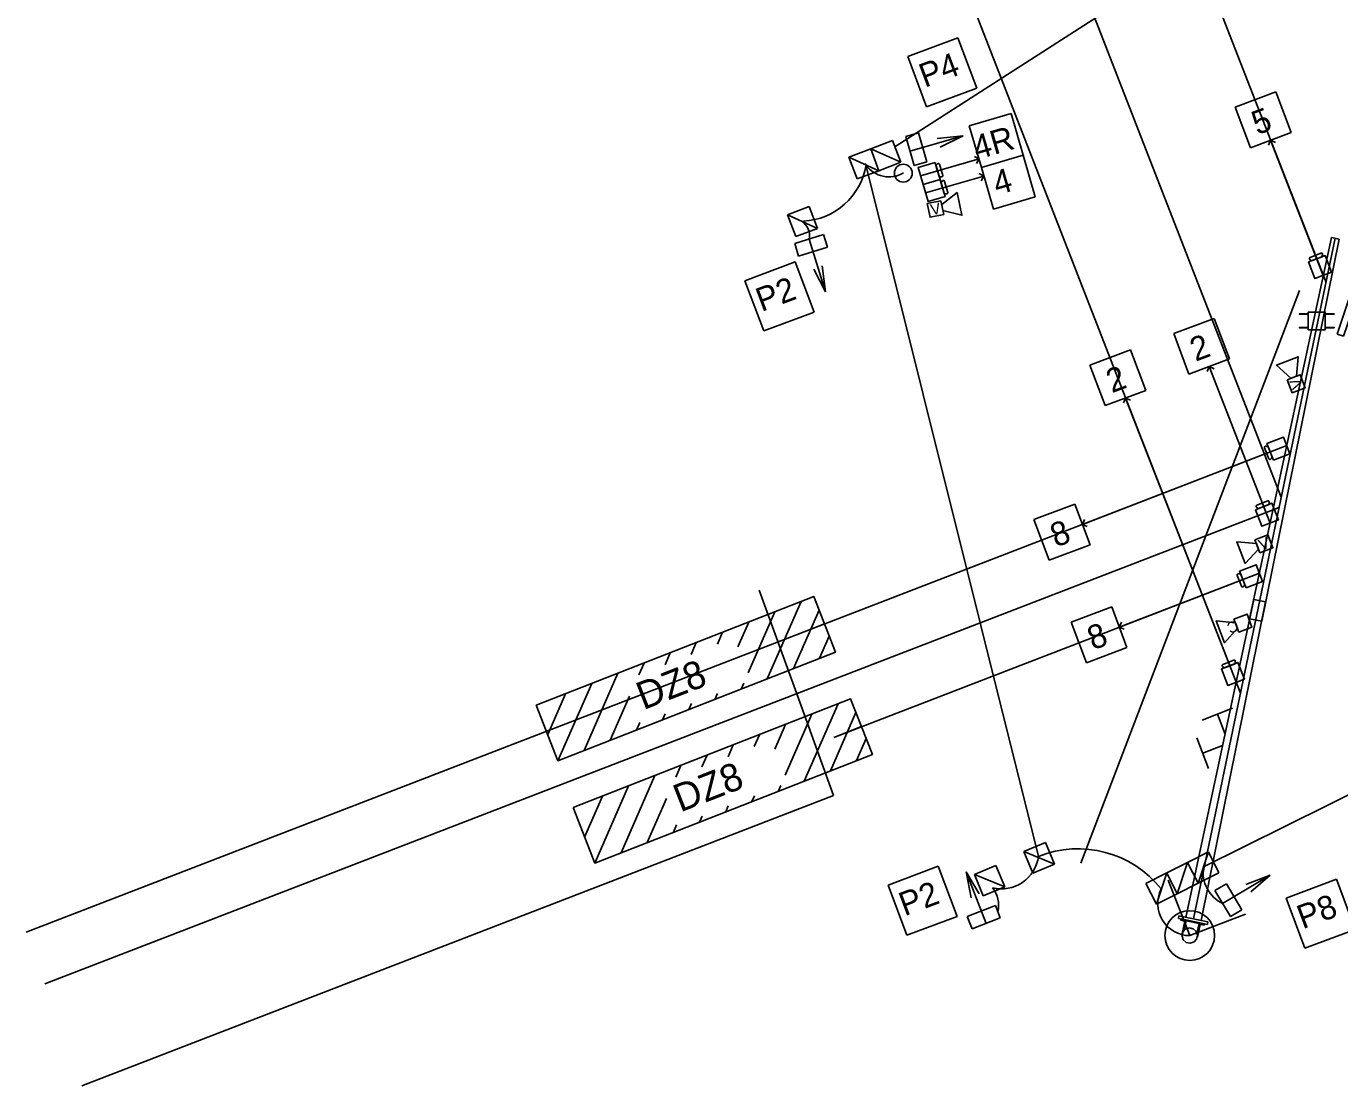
# Model space of a CAD drawing. Extents: x 510435 to 510719, y 1315254 to 1315553.
# Drawn here: x 510434.5 to 510566.7, y 1315372.5 to 1315479.2 of the extents above; entities that cross this region are included whole.
import ezdxf

# ---------------------------------------------------------------- set-up
doc = ezdxf.new("R2010")
doc.units = 0
for name, color, linetype in [('ConduitDB', 7, 'Continuous'), ('Default', 7, 'Continuous'), ('DetectorVeh', 7, 'Continuous'), ('NonPlottingEle_dp', 7, 'Continuous'), ('OverheadStr', 7, 'Continuous'), ('Pedestal', 7, 'Continuous'), ('PedHead', 7, 'Continuous'), ('PoleFound', 7, 'Continuous'), ('PullBox', 7, 'Continuous'), ('SignalHead', 7, 'Continuous'), ('SignSupport', 7, 'Continuous')]:
    doc.layers.add(name, color=color, linetype=linetype)

# ---------------------------------------------------------------- blocks, each defined once
blk = doc.blocks.new('VSVideoCamera')
at = {"layer": 'DetectorVeh'}
blk.add_line((0, -0.59), (0, 0.59), dxfattribs=at)
blk.add_lwpolyline([(0, 1.41), (-2.81, 1.41), (-2.81, -1.41), (0, -1.41)], close=True, dxfattribs=at)
blk.add_lwpolyline([(0, 0.59), (3.52, 2.34), (3.52, -2.34), (0, -0.59)], dxfattribs=at)
blk.add_text('V', height=2.25, dxfattribs=at).set_placement((-2.41, -1.12))
blk = doc.blocks.new('MastArmD4')
at = {"layer": 'OverheadStr'}
for p, q in [((0.25, 1.5), (0, 1.5)), ((0, 1.5), (0, -1.5)), ((0.25, 1.5), (0.25, -1.5)), ((0, -1.04), (0, 1.04)), ((0.25, 0.58), (11.7, 0.52)), ((9.7, 0.54), (46, 0.33)), ((9.7, 0.54), (9.7, -0.54)), ((11.7, 0.52), (11.7, -0.52)), ((46, 0.33), (46, -0.33)), ((0.25, -0.58), (11.7, -0.52)), ((9.7, -0.54), (46, -0.33)), ((0.25, -1.5), (0, -1.5))]:
    blk.add_line(p, q, dxfattribs=at)

msp = doc.modelspace()

# ---------------------------------------------------------------- linework, layer by layer
at = {"layer": 'ConduitDB'}
for p, q in [((510521.96, 1315467.05), (510573.34, 1315500.1)), ((510536.4, 1315395.61), (510519.01, 1315465.38)), ((510553, 1315394.55), (510617.23, 1315426.44))]:
    msp.add_line(p, q, dxfattribs=at)
at = {"layer": 'Default'}
for p, q in [((510509.11, 1315413.49), (510512.51, 1315421.26)), ((510507.19, 1315414.08), (510509.87, 1315420.23)), ((510511.74, 1315414.52), (510514.32, 1315420.4)), ((510504.09, 1315416.98), (510504.61, 1315418.17)), ((510506.15, 1315416.71), (510507.24, 1315419.2)), ((510501.45, 1315415.95), (510501.97, 1315417.14)), ((510514.38, 1315415.55), (510515.35, 1315417.77)), ((510498.82, 1315414.91), (510499.34, 1315416.1)), ((510490.67, 1315406.27), (510494.07, 1315414.04)), ((510496.19, 1315413.88), (510496.71, 1315415.07)), ((510488.04, 1315405.23), (510491.44, 1315413.01)), ((510506.48, 1315412.46), (510506.74, 1315413.05)), ((510487.01, 1315407.87), (510488.81, 1315411.98)), ((510493.31, 1315407.3), (510495.24, 1315411.73)), ((510503.84, 1315411.42), (510504.1, 1315412.02)), ((510501.21, 1315410.39), (510501.47, 1315410.99)), ((510512.83, 1315403.18), (510516.23, 1315410.96)), ((510515.46, 1315404.22), (510518.03, 1315410.1)), ((510495.94, 1315408.33), (510496.28, 1315409.09)), ((510498.58, 1315409.36), (510498.84, 1315409.96)), ((510509.87, 1315406.41), (510510.96, 1315408.9)), ((510510.9, 1315403.78), (510513.59, 1315409.93)), ((510507.8, 1315406.68), (510508.32, 1315407.86)), ((510518.09, 1315405.25), (510519.06, 1315407.47)), ((510505.17, 1315405.64), (510505.69, 1315406.83)), ((510499.9, 1315403.58), (510500.42, 1315404.77)), ((510502.54, 1315404.61), (510503.06, 1315405.8)), ((510494.39, 1315395.96), (510497.79, 1315403.74)), ((510491.76, 1315394.93), (510495.16, 1315402.71)), ((510510.19, 1315402.15), (510510.46, 1315402.75)), ((510490.73, 1315397.56), (510492.52, 1315401.67)), ((510497.03, 1315396.99), (510498.96, 1315401.42)), ((510507.56, 1315401.12), (510507.82, 1315401.72)), ((510502.29, 1315399.06), (510502.55, 1315399.66)), ((510504.93, 1315400.09), (510505.19, 1315400.69)), ((510499.66, 1315398.03), (510499.99, 1315398.79))]:
    msp.add_line(p, q, dxfattribs=at)
for points in [[(510485.85, 1315410.82), (510513.78, 1315421.76), (510515.97, 1315416.18), (510488.04, 1315405.23)], [(510489.57, 1315400.52), (510517.5, 1315411.46), (510519.69, 1315405.87), (510491.76, 1315394.93)]]:
    msp.add_lwpolyline(points, close=True, dxfattribs=at)
for centre, radius, start, end in [((510512.38, 1315466.33), 6.78, 273.1372, 350.3528), ((510521.37, 1315466.86), 2.84, 215.0224, 300.6598), ((510511.67, 1315458.13), 1.69, 347.7038, 57.3021), ((510532.66, 1315396.11), 3.78, 256.4983, 352.3938), ((510540.37, 1315385.65), 10.72, 38.5514, 111.6949), ((510556.51, 1315394.03), 3.54, 171.6762, 243.7101), ((510529.49, 1315390.66), 2.9, 347.5163, 37.787), ((510551.64, 1315390.87), 3.24, 153.2738, 269.8027)]:
    msp.add_arc(centre, radius, start, end, dxfattribs=at)
at = {"layer": 'DetectorVeh'}
msp.add_line((510556.43, 1315418.57), (510556.22, 1315419.12), dxfattribs=at)
msp.add_lwpolyline([(510556.22, 1315419.12), (510554.27, 1315419.31), (510555.11, 1315417.12), (510556.43, 1315418.57)], dxfattribs=at)
msp.add_lwpolyline([(510556.08, 1315419.5), (510557.39, 1315420.01), (510557.89, 1315418.7), (510556.58, 1315418.19)], close=True, dxfattribs=at)
at = {"layer": 'NonPlottingEle_dp'}
for p, q in [((510565.34, 1315453.4), (510526.58, 1315553.05)), ((510560.84, 1315431.79), (510515.57, 1315548.19)), ((510556.73, 1315412.03), (510505.5, 1315543.74)), ((510552, 1315389.31), (510566.27, 1315457.84)), ((510540.68, 1315394.94), (510562.66, 1315452.57)), ((510561.39, 1315436.98), (510434.54, 1315387.98)), ((510560.62, 1315430.74), (510436.42, 1315382.76)), ((510515.8, 1315407.58), (510558.66, 1315424.14)), ((510512.08, 1315411.99), (510508.31, 1315422.42)), ((510512.06, 1315417.93), (510514.86, 1315419.01)), ((510515.78, 1315401.74), (510512.08, 1315411.99)), ((510515.8, 1315407.58), (510518.6, 1315408.67)), ((510515.78, 1315401.74), (510440.12, 1315372.52))]:
    msp.add_line(p, q, dxfattribs=at)
at = {"layer": 'OverheadStr'}
for p, q in [((510559.56, 1315467.23), (510559.77, 1315467.72)), ((510565.06, 1315454.11), (510559.77, 1315467.72)), ((510560.26, 1315467.5), (510559.77, 1315467.72)), ((510529.95, 1315466.09), (510530.42, 1315465.83)), ((510530.16, 1315465.36), (510530.42, 1315465.83)), ((510526.42, 1315464.06), (510526.09, 1315465.18)), ((510526.78, 1315464.16), (510526.45, 1315465.29)), ((510526.78, 1315464.16), (510526.45, 1315465.29)), ((510530.44, 1315464.37), (510530.91, 1315464.11)), ((510526.92, 1315462.34), (510526.59, 1315463.47)), ((510527.28, 1315462.45), (510526.95, 1315463.57)), ((510527.28, 1315462.45), (510526.95, 1315463.57)), ((510530.65, 1315463.64), (510530.91, 1315464.11)), ((510557.65, 1315419.53), (510565.88, 1315457.92)), ((510566.65, 1315457.76), (510558.87, 1315419.28)), ((510566.65, 1315457.76), (510565.88, 1315457.92)), ((510564.83, 1315456.34), (510563.73, 1315455.92)), ((510564.83, 1315456.34), (510563.73, 1315455.92)), ((510564.96, 1315455.99), (510563.87, 1315455.57)), ((510553.38, 1315444.43), (510553.59, 1315444.92)), ((510559.72, 1315429.17), (510553.59, 1315444.92)), ((510554.08, 1315444.7), (510553.59, 1315444.92)), ((510544.95, 1315441.26), (510545.17, 1315441.76)), ((510555.52, 1315415.15), (510545.17, 1315441.76)), ((510545.66, 1315441.54), (510545.17, 1315441.76)), ((510559.16, 1315436.75), (510559.58, 1315435.65)), ((510559.16, 1315436.75), (510559.58, 1315435.65)), ((510559.51, 1315436.88), (510559.93, 1315435.79)), ((510559.37, 1315436.2), (510540.82, 1315429.03)), ((510559.48, 1315431.4), (510558.39, 1315430.97)), ((510559.48, 1315431.4), (510558.39, 1315430.97)), ((510559.62, 1315431.05), (510558.53, 1315430.62)), ((510541.03, 1315429.52), (510540.82, 1315429.03)), ((510541.31, 1315428.82), (510540.82, 1315429.03)), ((510558.64, 1315424.14), (510544.54, 1315418.69)), ((510556.41, 1315423.9), (510556.83, 1315422.81)), ((510556.41, 1315423.9), (510556.83, 1315422.81)), ((510556.76, 1315424.04), (510557.18, 1315422.94)), ((510551.23, 1315389.47), (510558.09, 1315421.48)), ((510559.25, 1315421.24), (510552.77, 1315389.15)), ((510559.25, 1315421.24), (510558.09, 1315421.48)), ((510557.65, 1315419.53), (510558.87, 1315419.28)), ((510544.76, 1315419.18), (510544.54, 1315418.69)), ((510545.03, 1315418.47), (510544.54, 1315418.69)), ((510556.06, 1315415.37), (510554.97, 1315414.94)), ((510556.06, 1315415.37), (510554.97, 1315414.94)), ((510556.2, 1315415.01), (510555.11, 1315414.59)), ((510550.49, 1315389.37), (510550.54, 1315389.62)), ((510553.41, 1315388.76), (510550.49, 1315389.37)), ((510553.46, 1315389.01), (510550.54, 1315389.62)), ((510550.72, 1315389.17), (510550.75, 1315389.32)), ((510550.72, 1315389.17), (510551.25, 1315389.06)), ((510550.75, 1315389.32), (510553.11, 1315388.83)), ((510550.86, 1315387.8), (510551.12, 1315389.08)), ((510550.9, 1315387.79), (510551.16, 1315389.07)), ((510551.05, 1315388.11), (510551.26, 1315389.13)), ((510551.26, 1315389.13), (510552.57, 1315388.86)), ((510553.41, 1315388.76), (510553.46, 1315389.01)), ((510550.86, 1315387.8), (510550.9, 1315387.79)), ((510552.35, 1315387.84), (510552.57, 1315388.86)), ((510552.36, 1315387.48), (510552.63, 1315388.77)), ((510552.41, 1315387.47), (510552.67, 1315388.76)), ((510552.55, 1315388.78), (510553.08, 1315388.67)), ((510553.08, 1315388.67), (510553.11, 1315388.83)), ((510552.41, 1315387.47), (510552.36, 1315387.48))]:
    msp.add_line(p, q, dxfattribs=at)
for points in [[(510526.01, 1315465.48), (510526.51, 1315463.76), (510524.79, 1315463.26), (510524.29, 1315464.98)], [(510526.51, 1315463.76), (510527.01, 1315462.05), (510525.29, 1315461.55), (510524.79, 1315463.26)], [(510563.58, 1315455.46), (510565.25, 1315456.1), (510565.9, 1315454.44), (510564.23, 1315453.79)], [(510560.04, 1315435.5), (510559.4, 1315437.17), (510561.07, 1315437.81), (510561.71, 1315436.15)], [(510558.24, 1315430.51), (510559.9, 1315431.16), (510560.55, 1315429.49), (510558.89, 1315428.84)], [(510557.3, 1315422.66), (510556.65, 1315424.32), (510558.32, 1315424.97), (510558.96, 1315423.3)], [(510554.82, 1315414.48), (510556.48, 1315415.13), (510557.13, 1315413.46), (510555.47, 1315412.81)], [(510551.59, 1315388.41), (510551.98, 1315388.33), (510552.28, 1315388.06), (510552.41, 1315387.68), (510552.32, 1315387.29), (510552.06, 1315386.99), (510551.67, 1315386.86), (510551.28, 1315386.94), (510550.98, 1315387.21), (510550.86, 1315387.59), (510550.94, 1315387.99), (510551.2, 1315388.28)]]:
    msp.add_lwpolyline(points, close=True, dxfattribs=at)
for points in [[(510526.09, 1315465.18), (510526.42, 1315464.06)], [(510526.59, 1315463.47), (510526.92, 1315462.34)], [(510563.87, 1315455.57), (510564.96, 1315455.99)], [(510559.93, 1315435.79), (510559.51, 1315436.88)], [(510558.53, 1315430.62), (510559.62, 1315431.05)], [(510557.18, 1315422.94), (510556.76, 1315424.04)], [(510555.11, 1315414.59), (510556.2, 1315415.01)]]:
    msp.add_lwpolyline(points, dxfattribs=at)
for centre, radius, start, end in [((510524.73, 1315466.84), 2.14, 309.4476, 315.5509), ((510526.34, 1315465.26), 0.115, 16.231, 135.5508), ((510526.16, 1315461.93), 2.14, 76.9112, 83.0145), ((510526.16, 1315461.93), 2.14, 76.9112, 83.0145), ((510525.23, 1315465.12), 2.14, 309.4476, 315.5509), ((510526.67, 1315464.13), 0.115, 256.9112, 16.231), ((510526.67, 1315464.13), 0.115, 256.9112, 16.231), ((510526.84, 1315463.54), 0.115, 16.231, 135.5508), ((510526.66, 1315460.22), 2.14, 76.9112, 83.0145), ((510526.66, 1315460.22), 2.14, 76.9112, 83.0145), ((510527.17, 1315462.42), 0.115, 256.9112, 16.231), ((510527.17, 1315462.42), 0.115, 256.9112, 16.231), ((510564.87, 1315456.24), 0.115, 351.9349, 111.2547), ((510564.87, 1315456.24), 0.115, 351.9349, 111.2547), ((510563.78, 1315455.81), 0.115, 111.2547, 230.5746), ((510563.78, 1315455.81), 0.115, 111.2547, 230.5745), ((510562.34, 1315454.07), 2.14, 44.4713, 50.5746), ((510562.34, 1315454.07), 2.14, 44.4713, 50.5746), ((510567.1, 1315455.92), 2.14, 171.9349, 178.0381), ((510567.1, 1315455.92), 2.14, 171.9349, 178.0381), ((510559.27, 1315436.79), 0.115, 81.8013, 201.1211), ((510559.27, 1315436.79), 0.115, 81.8013, 201.1211), ((510559.59, 1315439.02), 2.14, 261.8013, 267.9046), ((510559.59, 1315439.02), 2.14, 261.8013, 267.9046), ((510559.69, 1315435.69), 0.115, 201.1211, 320.441), ((510559.69, 1315435.69), 0.115, 201.1211, 320.4409), ((510561.43, 1315434.26), 2.14, 134.3377, 140.441), ((510561.43, 1315434.26), 2.14, 134.3377, 140.441), ((510559.52, 1315431.29), 0.115, 351.9349, 111.2547), ((510559.52, 1315431.29), 0.115, 351.9349, 111.2547), ((510561.76, 1315430.97), 2.14, 171.9349, 178.0381), ((510561.76, 1315430.97), 2.14, 171.9349, 178.0381), ((510558.43, 1315430.86), 0.115, 111.2547, 230.5746), ((510558.43, 1315430.86), 0.115, 111.2547, 230.5745), ((510557, 1315429.12), 2.14, 44.4713, 50.5746), ((510557, 1315429.12), 2.14, 44.4713, 50.5746), ((510556.52, 1315423.94), 0.115, 81.8013, 201.1211), ((510556.52, 1315423.94), 0.115, 81.8013, 201.1211), ((510556.84, 1315426.18), 2.14, 261.8013, 267.9046), ((510556.84, 1315426.18), 2.14, 261.8013, 267.9046), ((510556.94, 1315422.85), 0.115, 201.1211, 320.441), ((510556.94, 1315422.85), 0.115, 201.1211, 320.4409), ((510558.68, 1315421.41), 2.14, 134.3377, 140.441), ((510558.68, 1315421.41), 2.14, 134.3377, 140.441), ((510556.1, 1315415.26), 0.115, 351.9349, 111.2547), ((510556.1, 1315415.26), 0.115, 351.9349, 111.2547), ((510555.01, 1315414.83), 0.115, 111.2547, 230.5746), ((510555.01, 1315414.83), 0.115, 111.2547, 230.5745), ((510553.58, 1315413.09), 2.14, 44.4713, 50.5746), ((510553.58, 1315413.09), 2.14, 44.4713, 50.5746), ((510558.34, 1315414.94), 2.14, 171.9349, 178.0381), ((510558.34, 1315414.94), 2.14, 171.9349, 178.0381)]:
    msp.add_arc(centre, radius, start, end, dxfattribs=at)
at = {"layer": 'Pedestal'}
msp.add_circle((510522.8, 1315464.4), 0.9, dxfattribs=at)
at = {"layer": 'PedHead'}
for p, q in [((510523.25, 1315476.13), (510528.3, 1315478.02)), ((510528.3, 1315478.02), (510530.2, 1315472.97)), ((510523.25, 1315476.13), (510525.14, 1315471.07)), ((510525.14, 1315471.07), (510530.2, 1315472.97)), ((510556.19, 1315471.04), (510560.28, 1315472.58)), ((510560.28, 1315472.58), (510561.82, 1315468.49)), ((510556.19, 1315471.04), (510557.73, 1315466.95)), ((510529.44, 1315469.17), (510533.64, 1315470.4)), ((510533.64, 1315470.4), (510534.86, 1315466.2)), ((510523.05, 1315468.1), (510524.34, 1315468.46)), ((510524.34, 1315468.46), (510525.17, 1315465.53)), ((510529.44, 1315469.17), (510530.66, 1315464.97)), ((510557.73, 1315466.95), (510561.82, 1315468.49)), ((510523.88, 1315465.16), (510523.05, 1315468.1)), ((510523.46, 1315466.63), (510528.82, 1315468.15)), ((510528.82, 1315468.15), (510526.2, 1315467.88)), ((510528.82, 1315468.15), (510526.51, 1315467.03)), ((510530.66, 1315464.97), (510534.86, 1315466.2)), ((510530.66, 1315464.97), (510534.86, 1315466.2)), ((510534.86, 1315466.2), (510536.08, 1315462)), ((510525.17, 1315465.53), (510523.88, 1315465.16)), ((510530.66, 1315464.97), (510531.89, 1315460.77)), ((510531.89, 1315460.77), (510536.08, 1315462)), ((510511.87, 1315457.32), (510514.78, 1315458.22)), ((510513.32, 1315457.77), (510514.97, 1315452.45)), ((510514.78, 1315458.22), (510515.17, 1315456.94)), ((510512.26, 1315456.04), (510511.87, 1315457.32)), ((510515.17, 1315456.94), (510512.26, 1315456.04)), ((510506.86, 1315453.56), (510511.92, 1315455.46)), ((510511.92, 1315455.46), (510513.82, 1315450.41)), ((510514.97, 1315452.45), (510514.64, 1315455.07)), ((510514.97, 1315452.45), (510513.8, 1315454.73)), ((510506.86, 1315453.56), (510508.76, 1315448.51)), ((510508.76, 1315448.51), (510513.82, 1315450.41)), ((510550.01, 1315448.24), (510554.1, 1315449.78)), ((510554.1, 1315449.78), (510555.64, 1315445.69)), ((510550.01, 1315448.24), (510551.55, 1315444.15)), ((510541.58, 1315445.08), (510545.68, 1315446.62)), ((510545.68, 1315446.62), (510547.21, 1315442.52)), ((510541.58, 1315445.08), (510543.12, 1315440.99)), ((510551.55, 1315444.15), (510555.64, 1315445.69)), ((510543.12, 1315440.99), (510547.21, 1315442.52)), ((510535.95, 1315429.54), (510540.05, 1315431.08)), ((510540.05, 1315431.08), (510541.59, 1315426.98)), ((510535.95, 1315429.54), (510537.49, 1315425.45)), ((510537.49, 1315425.45), (510541.59, 1315426.98)), ((510539.68, 1315419.2), (510543.78, 1315420.74)), ((510543.78, 1315420.74), (510545.31, 1315416.64)), ((510539.68, 1315419.2), (510541.22, 1315415.1)), ((510541.22, 1315415.1), (510545.31, 1315416.64)), ((510521.26, 1315392.72), (510526.32, 1315394.61)), ((510526.32, 1315394.61), (510528.22, 1315389.56)), ((510529.11, 1315394.04), (510530.45, 1315391.85)), ((510531.14, 1315388.85), (510529.11, 1315394.04)), ((510529.11, 1315394.04), (510529.63, 1315391.45)), ((510554.94, 1315390.86), (510559.73, 1315393.71)), ((510559.73, 1315393.71), (510557.26, 1315392.77)), ((510559.73, 1315393.71), (510557.78, 1315392.03)), ((510561.32, 1315391.41), (510566.38, 1315393.31)), ((510566.38, 1315393.31), (510568.28, 1315388.26)), ((510521.26, 1315392.72), (510523.16, 1315387.66)), ((510554.16, 1315392.17), (510555.31, 1315392.86)), ((510555.72, 1315389.55), (510554.16, 1315392.17)), ((510555.31, 1315392.86), (510556.87, 1315390.24)), ((510529.24, 1315389.55), (510532.07, 1315390.66)), ((510532.07, 1315390.66), (510532.56, 1315389.41)), ((510556.87, 1315390.24), (510555.72, 1315389.55)), ((510561.32, 1315391.41), (510563.22, 1315386.36)), ((510523.16, 1315387.66), (510528.22, 1315389.56)), ((510529.73, 1315388.3), (510529.24, 1315389.55)), ((510532.56, 1315389.41), (510529.73, 1315388.3)), ((510563.22, 1315386.36), (510568.28, 1315388.26))]:
    msp.add_line(p, q, dxfattribs=at)
at = {"layer": 'PoleFound'}
for p, q in [((510530.42, 1315465.83), (510524.54, 1315464.12)), ((510530.91, 1315464.11), (510525.04, 1315462.41))]:
    msp.add_line(p, q, dxfattribs=at)
msp.add_circle((510551.63, 1315387.64), 2.5, dxfattribs=at)
at = {"layer": 'PullBox'}
for p, q in [((510519.52, 1315466.84), (510521.71, 1315467.68)), ((510521.71, 1315467.68), (510522.54, 1315465.49)), ((510517.33, 1315466.01), (510519.52, 1315466.84)), ((510518.16, 1315463.82), (510517.33, 1315466.01)), ((510520.35, 1315464.65), (510517.33, 1315466.01)), ((510520.35, 1315464.65), (510519.52, 1315466.84)), ((510522.54, 1315465.49), (510519.52, 1315466.84)), ((510519.52, 1315466.84), (510520.35, 1315464.65)), ((510520.35, 1315464.65), (510518.16, 1315463.82)), ((510522.54, 1315465.49), (510520.35, 1315464.65)), ((510511.15, 1315460.2), (510513.34, 1315461.03)), ((510513.34, 1315461.03), (510514.17, 1315458.84)), ((510511.98, 1315458.01), (510511.15, 1315460.2)), ((510514.17, 1315458.84), (510511.15, 1315460.2)), ((510514.17, 1315458.84), (510511.98, 1315458.01)), ((510534.93, 1315396.09), (510537.1, 1315396.99)), ((510537.1, 1315396.99), (510538, 1315394.82)), ((510535.84, 1315393.92), (510534.93, 1315396.09)), ((510534.93, 1315396.09), (510538, 1315394.82)), ((510551.41, 1315394.99), (510553.5, 1315396.05)), ((510552.47, 1315392.9), (510553.5, 1315396.05)), ((510553.5, 1315396.05), (510554.56, 1315393.96)), ((510529.95, 1315393.79), (510532.11, 1315394.69)), ((510532.11, 1315394.69), (510533.01, 1315392.53)), ((510538, 1315394.82), (510535.84, 1315393.92)), ((510549.32, 1315393.94), (510551.41, 1315394.99)), ((510550.37, 1315391.84), (510551.41, 1315394.99)), ((510552.47, 1315392.9), (510551.41, 1315394.99)), ((510551.41, 1315394.99), (510552.47, 1315392.9)), ((510530.85, 1315391.62), (510529.95, 1315393.79)), ((510529.95, 1315393.79), (510533.01, 1315392.53)), ((510547.22, 1315392.88), (510549.32, 1315393.94)), ((510548.28, 1315390.79), (510547.22, 1315392.88)), ((510548.28, 1315390.79), (510549.32, 1315393.94)), ((510549.32, 1315393.94), (510550.37, 1315391.84)), ((510550.37, 1315391.84), (510549.32, 1315393.94)), ((510552.47, 1315392.9), (510550.37, 1315391.84)), ((510554.56, 1315393.96), (510552.47, 1315392.9)), ((510533.01, 1315392.53), (510530.85, 1315391.62)), ((510550.37, 1315391.84), (510548.28, 1315390.79))]:
    msp.add_line(p, q, dxfattribs=at)
at = {"layer": 'SignalHead'}
for p, q in [((510563.56, 1315450.28), (510562.66, 1315450.23)), ((510562.66, 1315450.23), (510562.66, 1315450.19)), ((510562.66, 1315450.19), (510563.56, 1315450.19)), ((510565.26, 1315450.28), (510566.16, 1315450.23)), ((510566.16, 1315450.19), (510565.26, 1315450.19)), ((510566.16, 1315450.23), (510566.16, 1315450.19)), ((510562.66, 1315448.83), (510562.66, 1315448.86)), ((510562.66, 1315448.86), (510563.56, 1315448.86)), ((510563.56, 1315448.78), (510562.66, 1315448.83)), ((510566.16, 1315448.86), (510565.26, 1315448.86)), ((510565.26, 1315448.78), (510566.16, 1315448.83)), ((510566.16, 1315448.83), (510566.16, 1315448.86)), ((510552.88, 1315409.33), (510555.94, 1315410.52)), ((510554.41, 1315409.92), (510555.19, 1315407.92)), ((510553.52, 1315404.47), (510552.33, 1315407.53)), ((510552.93, 1315406), (510554.93, 1315406.78))]:
    msp.add_line(p, q, dxfattribs=at)
for points in [[(510563.56, 1315450.19), (510562.66, 1315450.19), (510562.66, 1315450.23), (510563.56, 1315450.28)], [(510565.26, 1315450.42), (510565.26, 1315448.63), (510563.56, 1315448.63), (510563.56, 1315450.42)], [(510565.26, 1315448.63), (510563.56, 1315448.63), (510563.56, 1315450.42), (510565.26, 1315450.42)], [(510565.26, 1315450.19), (510566.16, 1315450.19), (510566.16, 1315450.23), (510565.26, 1315450.28)], [(510563.56, 1315448.78), (510562.66, 1315448.83), (510562.66, 1315448.86), (510563.56, 1315448.86)], [(510565.26, 1315448.78), (510566.16, 1315448.83), (510566.16, 1315448.86), (510565.26, 1315448.86)]]:
    msp.add_lwpolyline(points, close=True, dxfattribs=at)
at = {"layer": 'SignSupport'}
for q in [(510549.47, 1315393.23), (510557.23, 1315389.79)]:
    msp.add_line((510551.63, 1315387.64), q, dxfattribs=at)

# ---------------------------------------------------------------- block references
at = {"layer": 'OverheadStr'}
for name, p, xscale, yscale, rotation in [('MastArmD4', (510582.8, 1315495.74), 1.0928961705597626, 0.9999999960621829, -108.57724603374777), ('VSVideoCamera', (510526.73, 1315460.94), 0.5, 0.49999999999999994, 11.960817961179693), ('VSVideoCamera', (510562.08, 1315443.85), 0.5, 0.5, 111.1211376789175), ('VSVideoCamera', (510558.44, 1315426.83), 0.4999999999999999, -0.5, -158.8788567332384)]:
    msp.add_blockref(name, p, dxfattribs=dict(at, xscale=xscale, yscale=yscale, rotation=rotation))

# ---------------------------------------------------------------- texts
at = {"layer": 'Default'}
for p in [(510496.64, 1315410.32), (510500.36, 1315400.02)]:
    msp.add_text('DZ8 ', height=2.8, rotation=21.3911, dxfattribs=at).set_placement(p)
at = {"layer": 'DetectorVeh'}
msp.add_text('C', height=1.12, rotation=201.1211, dxfattribs=at).set_placement((510556.27, 1315419.45))
at = {"layer": 'PedHead'}
for s, rotation, p in [('P4', 20.582, (510524.96, 1315472.99)), ('5', 20.582, (510558.42, 1315468.21)), ('4R', 16.231, (510530.22, 1315465.74)), ('4', 16.231, (510532.24, 1315462.17)), ('P2', 20.582, (510508.53, 1315450.41)), ('2', 20.582, (510552.21, 1315445.4)), ('2', 20.582, (510543.78, 1315442.23)), ('8', 20.582, (510538.16, 1315426.7)), ('8', 20.582, (510541.89, 1315416.35)), ('P2', 20.582, (510522.93, 1315389.56)), ('P8', 20.582, (510562.99, 1315388.26))]:
    msp.add_text(s, height=2.4, rotation=rotation, dxfattribs=at).set_placement(p)

doc.saveas('drawing.dxf')
